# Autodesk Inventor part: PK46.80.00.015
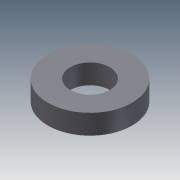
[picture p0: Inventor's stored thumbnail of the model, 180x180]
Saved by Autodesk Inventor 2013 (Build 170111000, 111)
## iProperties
Shininess: 64.0
Length Units: 11269
Angle Units: 11279
Time Units: 11290
Mass Units: 11283
Length Display Precision: 3
Angle Display Precision: 2
Compacted: True
Part Number: PK46.80.00.015
Document SubType Name: Modeling
Created: 2005-01
Material: Steel, Mild
Designer: SAlex
Manufacturer: Standard
Standards Organization: Custom
Density: 7.86 g/cm^3
Mass: 5555.91 g
Surface Area: 667.588 cm^2
Volume: 706.858 cm^3
Density: 0.0
Volumn: 0.0
Area: 0.0
PropertySet Name: Model Information
Control State: 0
Master: False
Checked Out: False
Checked Out Date: 2008-10-15
Last Check In Date: 2008-10-15
Author: SAlex
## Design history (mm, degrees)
sketch "Sketch1"
  geometry: C1 r 40 at (0, 0); C2 r 85 at (0, 0)
  constraints: 2 centre point, 1 coincident, 1 other
  dimensions: "d0" = 80 diameter of C1; "d1" = 170 diameter of C2
extrude "Extrusion1" new body sketch "Sketch1" distance "d2" = 40; taper "d3" = 0 deg
body "Solid1"
